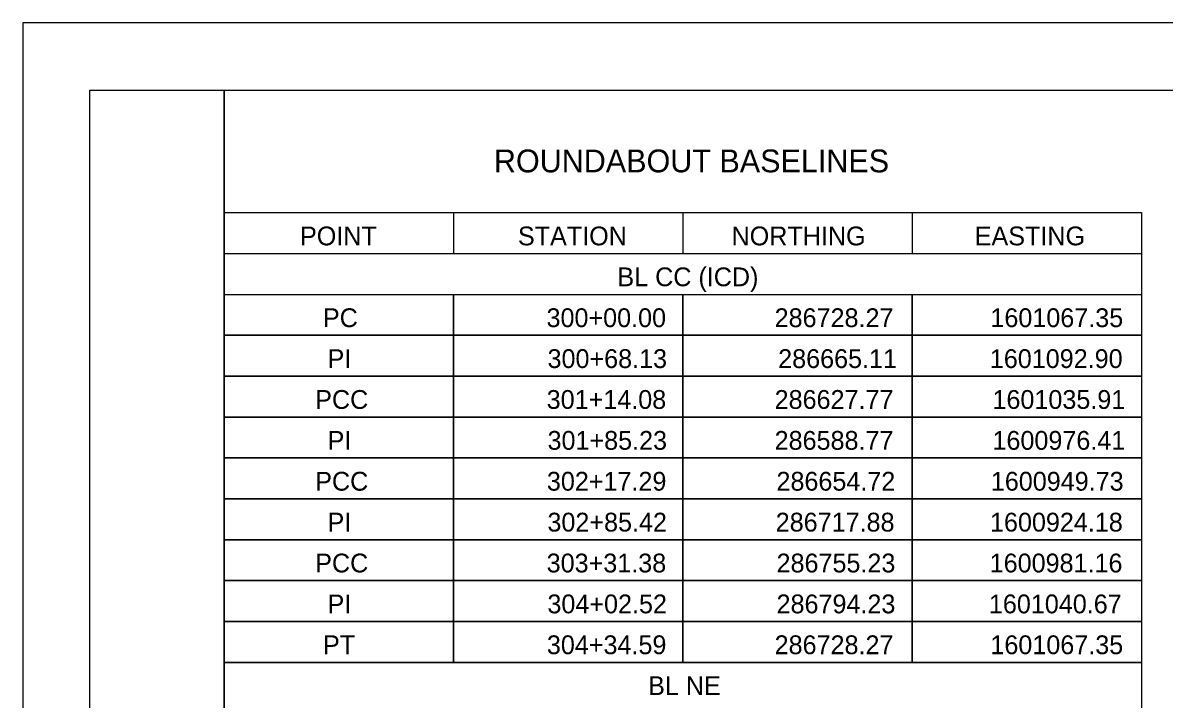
# Model space of a CAD drawing. Extents: x 0 to 34, y 0 to 22.
# Drawn here: x 0 to 8.5, y 16.97 to 22 of the extents above; entities that cross this region are included whole.
import ezdxf

# ---------------------------------------------------------------- set-up
doc = ezdxf.new("R2010")
doc.units = 0
for name, color, linetype in [('SH_Border', 7, 'Continuous'), ('SH_Cut_Line', 7, 'Continuous'), ('SH_Text', 7, 'Continuous')]:
    doc.layers.add(name, color=color, linetype=linetype)

msp = doc.modelspace()

# ---------------------------------------------------------------- linework, layer by layer
at = {"layer": 'SH_Border'}
for points in [[(0.5, 21.5), (1.5, 21.5), (1.5, 0.5), (0.5, 0.5)], [(1.5, 21.5), (33.5, 21.5), (33.5, 0.5), (1.5, 0.5)]]:
    msp.add_lwpolyline(points, close=True, dxfattribs=at)
at = {"layer": 'SH_Cut_Line'}
msp.add_lwpolyline([(0, 0), (34, 0), (34, 22), (0, 22)], close=True, dxfattribs=at)
at = {"layer": 'SH_Text'}
for p, q in [((1.5, 20.587), (8.3309, 20.587)), ((1.5, 20.587), (1.5, 19.9783)), ((3.2077, 20.587), (3.2077, 20.2826)), ((4.9155, 20.587), (4.9155, 20.2826)), ((6.6232, 20.587), (6.6232, 20.2826)), ((8.3309, 20.587), (8.3309, 19.9783)), ((1.5, 20.2826), (8.3309, 20.2826)), ((1.5, 19.9783), (8.3309, 19.9783)), ((1.5, 19.9783), (1.5, 17.2391)), ((3.2077, 19.9783), (3.2077, 17.2391)), ((4.9155, 19.9783), (4.9155, 17.2391)), ((6.6232, 19.9783), (6.6232, 17.2391)), ((8.3309, 19.9783), (8.3309, 17.2391)), ((1.5, 19.6739), (8.3309, 19.6739)), ((1.5, 19.3696), (8.3309, 19.3696)), ((1.5, 19.0652), (8.3309, 19.0652)), ((1.5, 18.7609), (8.3309, 18.7609)), ((1.5, 18.4565), (8.3309, 18.4565)), ((1.5, 18.1522), (8.3309, 18.1522)), ((1.5, 17.8478), (8.3309, 17.8478)), ((1.5, 17.5435), (8.3309, 17.5435)), ((1.5, 17.2391), (8.3309, 17.2391)), ((1.5, 17.2391), (1.5, 16.3261)), ((8.3309, 17.2391), (8.3309, 16.3261))]:
    msp.add_line(p, q, dxfattribs=at)
for points in [[(1.5, 19.9783), (3.2077, 19.9783), (3.2077, 19.6739), (1.5, 19.6739)], [(3.2077, 19.9783), (4.9155, 19.9783), (4.9155, 19.6739), (3.2077, 19.6739)], [(4.9155, 19.9783), (6.6232, 19.9783), (6.6232, 19.6739), (4.9155, 19.6739)], [(6.6232, 19.9783), (8.3309, 19.9783), (8.3309, 19.6739), (6.6232, 19.6739)], [(1.5, 19.6739), (3.2077, 19.6739), (3.2077, 19.3696), (1.5, 19.3696)], [(3.2077, 19.6739), (4.9155, 19.6739), (4.9155, 19.3696), (3.2077, 19.3696)], [(4.9155, 19.6739), (6.6232, 19.6739), (6.6232, 19.3696), (4.9155, 19.3696)], [(6.6232, 19.6739), (8.3309, 19.6739), (8.3309, 19.3696), (6.6232, 19.3696)], [(1.5, 19.3696), (3.2077, 19.3696), (3.2077, 19.0652), (1.5, 19.0652)], [(3.2077, 19.3696), (4.9155, 19.3696), (4.9155, 19.0652), (3.2077, 19.0652)], [(4.9155, 19.3696), (6.6232, 19.3696), (6.6232, 19.0652), (4.9155, 19.0652)], [(6.6232, 19.3696), (8.3309, 19.3696), (8.3309, 19.0652), (6.6232, 19.0652)], [(1.5, 19.0652), (3.2077, 19.0652), (3.2077, 18.7609), (1.5, 18.7609)], [(3.2077, 19.0652), (4.9155, 19.0652), (4.9155, 18.7609), (3.2077, 18.7609)], [(4.9155, 19.0652), (6.6232, 19.0652), (6.6232, 18.7609), (4.9155, 18.7609)], [(6.6232, 19.0652), (8.3309, 19.0652), (8.3309, 18.7609), (6.6232, 18.7609)], [(1.5, 18.7609), (3.2077, 18.7609), (3.2077, 18.4565), (1.5, 18.4565)], [(3.2077, 18.7609), (4.9155, 18.7609), (4.9155, 18.4565), (3.2077, 18.4565)], [(4.9155, 18.7609), (6.6232, 18.7609), (6.6232, 18.4565), (4.9155, 18.4565)], [(6.6232, 18.7609), (8.3309, 18.7609), (8.3309, 18.4565), (6.6232, 18.4565)], [(1.5, 18.4565), (3.2077, 18.4565), (3.2077, 18.1522), (1.5, 18.1522)], [(3.2077, 18.4565), (4.9155, 18.4565), (4.9155, 18.1522), (3.2077, 18.1522)], [(4.9155, 18.4565), (6.6232, 18.4565), (6.6232, 18.1522), (4.9155, 18.1522)], [(6.6232, 18.4565), (8.3309, 18.4565), (8.3309, 18.1522), (6.6232, 18.1522)], [(1.5, 18.1522), (3.2077, 18.1522), (3.2077, 17.8478), (1.5, 17.8478)], [(3.2077, 18.1522), (4.9155, 18.1522), (4.9155, 17.8478), (3.2077, 17.8478)], [(4.9155, 18.1522), (6.6232, 18.1522), (6.6232, 17.8478), (4.9155, 17.8478)], [(6.6232, 18.1522), (8.3309, 18.1522), (8.3309, 17.8478), (6.6232, 17.8478)], [(1.5, 17.8478), (3.2077, 17.8478), (3.2077, 17.5435), (1.5, 17.5435)], [(3.2077, 17.8478), (4.9155, 17.8478), (4.9155, 17.5435), (3.2077, 17.5435)], [(4.9155, 17.8478), (6.6232, 17.8478), (6.6232, 17.5435), (4.9155, 17.5435)], [(6.6232, 17.8478), (8.3309, 17.8478), (8.3309, 17.5435), (6.6232, 17.5435)], [(1.5, 17.5435), (3.2077, 17.5435), (3.2077, 17.2391), (1.5, 17.2391)], [(3.2077, 17.5435), (4.9155, 17.5435), (4.9155, 17.2391), (3.2077, 17.2391)], [(4.9155, 17.5435), (6.6232, 17.5435), (6.6232, 17.2391), (4.9155, 17.2391)], [(6.6232, 17.5435), (8.3309, 17.5435), (8.3309, 17.2391), (6.6232, 17.2391)]]:
    msp.add_lwpolyline(points, close=True, dxfattribs=at)

# ---------------------------------------------------------------- texts
for s, height, p in [('ROUNDABOUT BASELINES', 0.17, (3.5087, 20.887)), ('POINT', 0.14, (2.0644, 20.3435)), ('STATION', 0.14, (3.6878, 20.3435)), ('NORTHING', 0.14, (5.2786, 20.3435)), ('EASTING', 0.14, (7.0899, 20.3435)), ('BL CC (ICD)', 0.14, (4.4285, 20.0391)), ('PC', 0.14, (2.2352, 19.7348)), ('300+00.00', 0.14, (3.9006, 19.7348)), ('286728.27', 0.14, (5.5995, 19.7348)), ('1601067.35', 0.14, (7.2066, 19.7348)), ('PI', 0.14, (2.2696, 19.4304)), ('300+68.13', 0.14, (3.9081, 19.4304)), ('286665.11', 0.14, (5.626, 19.4304)), ('1601092.90', 0.14, (7.2024, 19.4304)), ('PCC', 0.14, (2.1776, 19.1261)), ('301+14.08', 0.14, (3.9017, 19.1261)), ('286627.77', 0.14, (5.5995, 19.1261)), ('1601035.91', 0.14, (7.222, 19.1261)), ('PI', 0.14, (2.2696, 18.8217)), ('301+85.23', 0.14, (3.9081, 18.8217)), ('286588.77', 0.14, (5.5995, 18.8217)), ('1600976.41', 0.14, (7.222, 18.8217)), ('PCC', 0.14, (2.1776, 18.5174)), ('302+17.29', 0.14, (3.9033, 18.5174)), ('286654.72', 0.14, (5.6132, 18.5174)), ('1600949.73', 0.14, (7.2099, 18.5174)), ('PI', 0.14, (2.2696, 18.213)), ('302+85.42', 0.14, (3.9073, 18.213)), ('286717.88', 0.14, (5.6076, 18.213)), ('1600924.18', 0.14, (7.2036, 18.213)), ('PCC', 0.14, (2.1776, 17.9087)), ('303+31.38', 0.14, (3.9017, 17.9087)), ('286755.23', 0.14, (5.6139, 17.9087)), ('1600981.16', 0.14, (7.2013, 17.9087)), ('PI', 0.14, (2.2696, 17.6043)), ('304+02.52', 0.14, (3.9073, 17.6043)), ('286794.23', 0.14, (5.6139, 17.6043)), ('1601040.67', 0.14, (7.1955, 17.6043)), ('PT', 0.14, (2.2359, 17.3)), ('304+34.59', 0.14, (3.9033, 17.3)), ('286728.27', 0.14, (5.5995, 17.3)), ('1601067.35', 0.14, (7.2066, 17.3)), ('BL NE', 0.14, (4.6572, 16.9957))]:
    msp.add_text(s, height=height, dxfattribs=at).set_placement(p)

doc.saveas('drawing.dxf')
